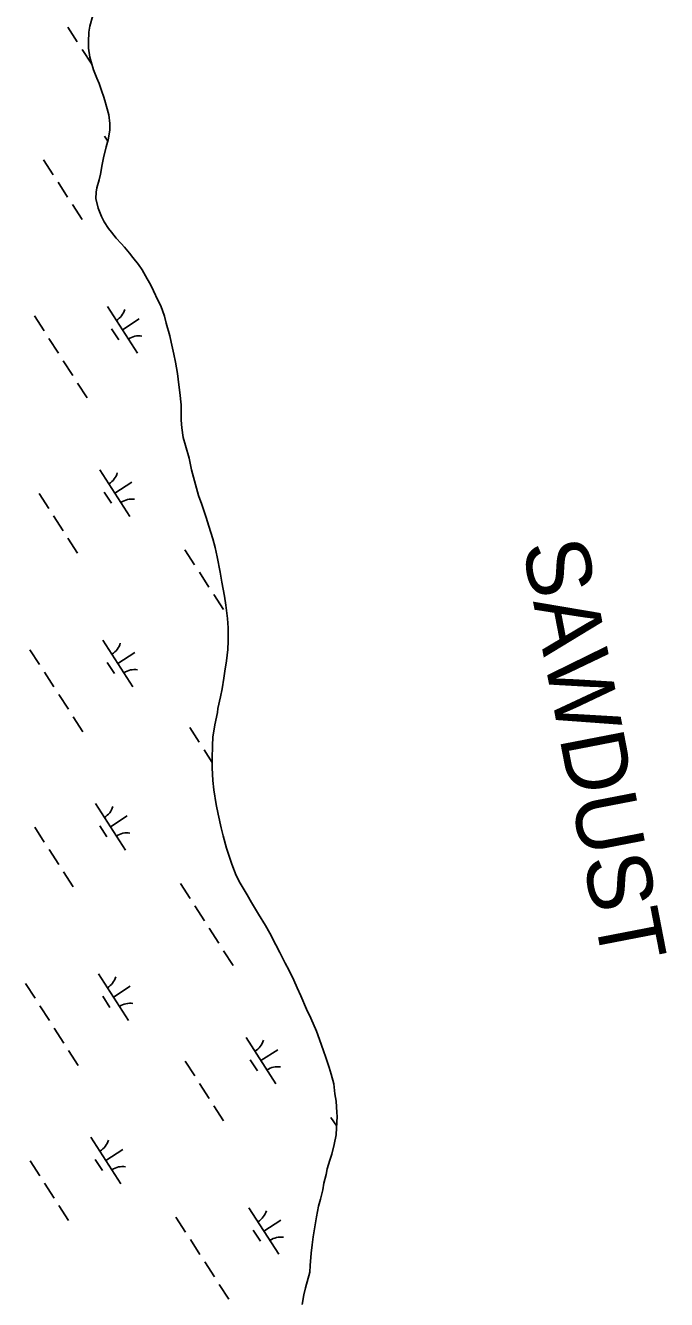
# Model space of a CAD drawing. Extents: x 3937982 to 3958556, y 219448 to 241894.
# Drawn here: x 3949983 to 3950561, y 230898 to 232047 of the extents above; entities that cross this region are included whole.
import ezdxf

# ---------------------------------------------------------------- set-up
doc = ezdxf.new("R2010")
doc.units = 0
for name, color, linetype in [('V-RIVR-IDEN', 7, 'Continuous'), ('V-TOPO-SHOR', 7, 'Continuous'), ('V-WETL-SWMP', 7, 'Continuous')]:
    doc.layers.add(name, color=color, linetype=linetype)

msp = doc.modelspace()

# ---------------------------------------------------------------- linework, layer by layer
at = {"layer": 'V-TOPO-SHOR'}
for points in [[(3950039.605, 232032.615), (3950039.955, 232041.17), (3950040.903, 232046.615), (3950043.39, 232056.149)], [(3950199.304, 231235.325), (3950193.039, 231245.597), (3950186.774, 231256.065), (3950182.666, 231262.85), (3950176.401, 231273.317), (3950172.87, 231280.493), (3950168.748, 231290.582), (3950167.566, 231294.074), (3950164.021, 231304.942), (3950161.057, 231316.008), (3950159.276, 231323.385), (3950156.697, 231335.617), (3950154.715, 231344.549), (3950152.714, 231357.754), (3950151.706, 231366.108), (3950151.268, 231377.573), (3950151.233, 231385.539), (3950151.377, 231397.59), (3950151.733, 231405.171), (3950153.627, 231416.257), (3950155.913, 231427.345), (3950156.286, 231431.04), (3950158.571, 231441.544), (3950160.095, 231448.741), (3950161.608, 231458.464), (3950162.552, 231464.688), (3950164.068, 231474.023), (3950165.188, 231484.134), (3950165.545, 231491.908), (3950165.493, 231503.764), (3950164.875, 231512.118), (3950163.462, 231524.16), (3950162.26, 231532.317), (3950159.874, 231545.136), (3950158.475, 231554.069), (3950155.694, 231567.854), (3950153.908, 231576.204), (3950151.737, 231584.163), (3950148.188, 231595.615), (3950145.822, 231603.379), (3950141.884, 231615.022), (3950138.935, 231623.171), (3950132.615, 231646.465), (3950130.432, 231656.95), (3950127.079, 231668.208), (3950125.105, 231675.585), (3950123.706, 231684.129), (3950123.094, 231691.123), (3950123.063, 231698.508), (3950123.032, 231705.115), (3950121.82, 231716.189), (3950121.207, 231722.988), (3950119.995, 231733.284), (3950118.203, 231743.577), (3950116.618, 231750.565), (3950114.044, 231761.437), (3950112.854, 231767.264), (3950109.696, 231778.522), (3950108.113, 231784.928), (3950104.768, 231794.242), (3950102.22, 231799.284), (3950098.102, 231807.816), (3950095.55, 231813.442), (3950092.613, 231818.677), (3950087.913, 231826.82), (3950084.784, 231831.471), (3950079.705, 231837.861), (3950076.577, 231841.93), (3950072.084, 231847.156), (3950069.155, 231850.448), (3950064.662, 231855.482), (3950060.171, 231860.71), (3950057.629, 231864.198), (3950053.716, 231870.205), (3950051.17, 231874.858), (3950048.221, 231882.425), (3950046.046, 231891.162), (3950046.41, 231896.798), (3950047.17, 231900.884), (3950049.081, 231908.082), (3950050.42, 231913.141), (3950051.94, 231921.697), (3950053.079, 231927.729), (3950055.563, 231937.649), (3950057.283, 231944.072), (3950058.801, 231952.823), (3950058.774, 231958.654), (3950057.769, 231966.616), (3950055.794, 231973.993), (3950054.41, 231979.431), (3950053.032, 231983.504), (3950051.653, 231987.774), (3950049.095, 231994.76), (3950046.937, 231999.804), (3950044.184, 232007.177), (3950041.821, 232014.552), (3950040.832, 232018.629), (3950039.629, 232026.787), (3950039.605, 232032.615)], [(3950232.264, 230893.419), (3950233.782, 230902.172), (3950235.504, 230908.398), (3950239.135, 230922.601), (3950239.692, 230928.628), (3950240.422, 230939.708), (3950241.362, 230947.097), (3950242.302, 230954.486), (3950243.436, 230961.489), (3950245.333, 230972.38), (3950247.041, 230982.106), (3950248.761, 230988.332), (3950250.862, 230996.89), (3950252.003, 231002.922), (3950253.914, 231010.51), (3950255.057, 231015.761), (3950257.356, 231023.545), (3950259.081, 231028.995), (3950261.182, 231037.553), (3950262.894, 231046.307), (3950263.449, 231052.723), (3950263.793, 231063.024), (3950263.779, 231066.522), (3950262.956, 231076.82), (3950261.956, 231083.23), (3950260.945, 231092.36), (3950258.575, 231101.095), (3950256.799, 231107.112), (3950253.846, 231116.039), (3950251.681, 231122.248), (3950248.138, 231132.533), (3950245.191, 231139.904), (3950240.09, 231151.543), (3950236.168, 231159.69), (3950231.062, 231171.718), (3950227.921, 231178.894), (3950224.976, 231185.878), (3950220.271, 231195.186), (3950216.941, 231201.197), (3950212.237, 231210.892), (3950208.706, 231217.874), (3950203.22, 231228.345), (3950199.304, 231235.325)]]:
    msp.add_lwpolyline(points, dxfattribs=at)
at = {"layer": 'V-WETL-SWMP'}
for p, q in [((3950020.778, 232045.823), (3950029.438, 232032.369)), ((3950040.904, 232046.615), (3950039.956, 232041.169)), ((3950043.389, 232056.148), (3950040.904, 232046.615)), ((3950039.956, 232041.169), (3950039.604, 232032.616)), ((3950033.768, 232025.642), (3950042.428, 232012.189)), ((3950039.604, 232032.616), (3950039.629, 232026.786)), ((3950039.629, 232026.786), (3950040.831, 232018.629)), ((3950040.831, 232018.629), (3950041.82, 232014.552)), ((3950041.82, 232014.552), (3950044.184, 232007.177)), ((3950044.184, 232007.177), (3950046.937, 231999.804)), ((3950046.937, 231999.804), (3950049.096, 231994.76)), ((3950049.096, 231994.76), (3950051.653, 231987.775)), ((3950051.653, 231987.775), (3950053.032, 231983.505)), ((3950053.032, 231983.505), (3950054.41, 231979.43)), ((3950054.41, 231979.43), (3950055.794, 231973.994)), ((3950055.794, 231973.994), (3950057.769, 231966.617)), ((3950057.769, 231966.617), (3950058.775, 231958.654)), ((3950058.775, 231958.654), (3950058.801, 231952.823)), ((3950053.926, 231947.452), (3950056.936, 231942.774)), ((3950057.284, 231944.071), (3950055.562, 231937.65)), ((3950058.801, 231952.823), (3950057.284, 231944.071)), ((3950055.562, 231937.65), (3950053.079, 231927.728)), ((3949999.06, 231926.054), (3950007.72, 231912.601)), ((3950051.939, 231921.698), (3950050.421, 231913.141)), ((3950053.079, 231927.728), (3950051.939, 231921.698)), ((3950049.082, 231908.082), (3950047.17, 231900.883)), ((3950050.421, 231913.141), (3950049.082, 231908.082)), ((3950012.049, 231905.874), (3950020.709, 231892.42)), ((3950046.41, 231896.798), (3950046.046, 231891.161)), ((3950047.17, 231900.883), (3950046.41, 231896.798)), ((3950025.039, 231885.693), (3950033.699, 231872.239)), ((3950046.046, 231891.161), (3950048.221, 231882.425)), ((3950048.221, 231882.425), (3950051.169, 231874.858)), ((3950051.169, 231874.858), (3950053.716, 231870.205)), ((3950053.716, 231870.205), (3950057.629, 231864.197)), ((3950057.629, 231864.197), (3950060.17, 231860.71)), ((3950060.17, 231860.71), (3950064.663, 231855.482)), ((3950064.663, 231855.482), (3950069.155, 231850.448)), ((3950069.155, 231850.448), (3950072.084, 231847.157)), ((3950072.084, 231847.157), (3950076.577, 231841.929)), ((3950076.577, 231841.929), (3950079.704, 231837.861)), ((3950079.704, 231837.861), (3950084.784, 231831.47)), ((3950084.784, 231831.47), (3950087.914, 231826.819)), ((3950087.914, 231826.819), (3950092.613, 231818.677)), ((3950092.613, 231818.677), (3950095.551, 231813.442)), ((3950095.551, 231813.442), (3950098.102, 231807.817)), ((3950098.102, 231807.817), (3950102.22, 231799.284)), ((3950056.624, 231793.732), (3950083.687, 231751.689)), ((3950102.22, 231799.284), (3950104.768, 231794.242)), ((3950104.768, 231794.242), (3950108.112, 231784.928)), ((3949990.759, 231785.137), (3949999.419, 231771.683)), ((3950070.155, 231772.71), (3950085.291, 231782.453)), ((3950108.112, 231784.928), (3950109.695, 231778.521)), ((3950060.42, 231773.579), (3950066.915, 231763.489)), ((3950109.695, 231778.521), (3950112.853, 231767.263)), ((3950003.749, 231764.956), (3950012.409, 231751.502)), ((3950112.853, 231767.263), (3950114.044, 231761.438)), ((3950114.044, 231761.438), (3950116.618, 231750.565)), ((3950116.618, 231750.565), (3950118.203, 231743.576)), ((3950016.739, 231744.775), (3950025.399, 231731.322)), ((3950118.203, 231743.576), (3950119.996, 231733.283)), ((3950029.729, 231724.595), (3950038.389, 231711.141)), ((3950119.996, 231733.283), (3950121.207, 231722.988)), ((3950121.207, 231722.988), (3950121.819, 231716.189)), ((3950121.819, 231716.189), (3950123.033, 231705.116)), ((3950123.033, 231705.116), (3950123.062, 231698.509)), ((3950123.062, 231698.509), (3950123.094, 231691.124)), ((3950123.094, 231691.124), (3950123.707, 231684.13)), ((3950123.707, 231684.13), (3950125.104, 231675.585)), ((3950125.104, 231675.585), (3950127.08, 231668.208)), ((3950127.08, 231668.208), (3950130.432, 231656.951)), ((3950130.432, 231656.951), (3950132.615, 231646.465)), ((3950049.886, 231646.404), (3950076.949, 231604.361)), ((3950132.615, 231646.465), (3950138.935, 231623.171)), ((3950063.417, 231625.382), (3950078.553, 231635.125)), ((3949995.02, 231625.007), (3950003.68, 231611.553)), ((3950053.682, 231626.251), (3950060.177, 231616.161)), ((3950138.935, 231623.171), (3950141.885, 231615.022)), ((3950141.885, 231615.022), (3950145.823, 231603.378)), ((3950008.01, 231604.826), (3950016.67, 231591.372)), ((3950145.823, 231603.378), (3950148.188, 231595.614)), ((3950148.188, 231595.614), (3950151.736, 231584.163)), ((3950021, 231584.645), (3950029.66, 231571.191)), ((3950126.587, 231574.119), (3950135.247, 231560.665)), ((3950151.736, 231584.163), (3950153.908, 231576.204)), ((3950153.908, 231576.204), (3950155.693, 231567.855)), ((3950155.693, 231567.855), (3950158.474, 231554.069)), ((3950139.577, 231553.938), (3950148.237, 231540.484)), ((3950158.474, 231554.069), (3950159.873, 231545.135)), ((3950159.873, 231545.135), (3950162.26, 231532.318)), ((3950152.567, 231533.757), (3950161.227, 231520.303)), ((3950162.26, 231532.318), (3950163.462, 231524.161)), ((3950163.462, 231524.161), (3950164.874, 231512.118)), ((3950164.874, 231512.118), (3950165.493, 231503.764)), ((3950165.493, 231503.764), (3950165.544, 231491.909)), ((3949986.72, 231484.089), (3949995.38, 231470.635)), ((3950052.585, 231492.684), (3950079.647, 231450.641)), ((3950165.189, 231484.134), (3950164.067, 231474.023)), ((3950165.544, 231491.909), (3950165.189, 231484.134)), ((3950056.381, 231472.532), (3950062.876, 231462.441)), ((3950066.116, 231471.662), (3950081.252, 231481.405)), ((3950164.067, 231474.023), (3950162.553, 231464.688)), ((3949999.71, 231463.908), (3950008.37, 231450.455)), ((3950162.553, 231464.688), (3950161.608, 231458.464)), ((3950160.095, 231448.741), (3950158.571, 231441.543)), ((3950161.608, 231458.464), (3950160.095, 231448.741)), ((3950012.7, 231443.728), (3950021.36, 231430.274)), ((3950158.571, 231441.543), (3950156.285, 231431.039)), ((3950155.912, 231427.345), (3950153.628, 231416.257)), ((3950156.285, 231431.039), (3950155.912, 231427.345)), ((3950025.69, 231423.547), (3950034.349, 231410.093)), ((3950130.848, 231413.988), (3950139.508, 231400.535)), ((3950153.628, 231416.257), (3950151.732, 231405.171)), ((3950151.732, 231405.171), (3950151.376, 231397.59)), ((3950143.838, 231393.808), (3950151.248, 231382.296)), ((3950151.376, 231397.59), (3950151.234, 231385.54)), ((3950151.234, 231385.54), (3950151.268, 231377.572)), ((3950151.268, 231377.572), (3950151.706, 231366.108)), ((3950151.706, 231366.108), (3950152.714, 231357.755)), ((3950152.714, 231357.755), (3950154.715, 231344.548)), ((3950045.847, 231345.356), (3950072.909, 231303.313)), ((3950154.715, 231344.548), (3950156.697, 231335.617)), ((3950059.378, 231324.334), (3950074.514, 231334.077)), ((3950156.697, 231335.617), (3950159.276, 231323.384)), ((3949990.981, 231323.959), (3949999.641, 231310.505)), ((3950049.643, 231325.204), (3950056.138, 231315.113)), ((3950159.276, 231323.384), (3950161.057, 231316.007)), ((3950161.057, 231316.007), (3950164.02, 231304.942)), ((3950003.971, 231303.778), (3950012.631, 231290.324)), ((3950164.02, 231304.942), (3950167.565, 231294.074)), ((3950167.565, 231294.074), (3950168.747, 231290.581)), ((3950168.747, 231290.581), (3950172.871, 231280.493)), ((3950016.961, 231283.597), (3950025.62, 231270.144)), ((3950172.871, 231280.493), (3950176.401, 231273.317)), ((3950122.548, 231273.071), (3950131.208, 231259.617)), ((3950176.401, 231273.317), (3950182.665, 231262.85)), ((3950135.538, 231252.89), (3950144.198, 231239.436)), ((3950182.665, 231262.85), (3950186.775, 231256.065)), ((3950186.775, 231256.065), (3950193.04, 231245.598)), ((3950193.04, 231245.598), (3950199.303, 231235.325)), ((3950148.527, 231232.709), (3950157.187, 231219.256)), ((3950199.303, 231235.325), (3950203.22, 231228.345)), ((3950203.22, 231228.345), (3950208.707, 231217.874)), ((3950208.707, 231217.874), (3950212.236, 231210.893)), ((3950161.517, 231212.529), (3950170.177, 231199.075)), ((3950212.236, 231210.893), (3950216.942, 231201.196)), ((3950216.942, 231201.196), (3950220.272, 231195.186)), ((3950220.272, 231195.186), (3950224.976, 231185.878)), ((3950048.545, 231191.636), (3950075.608, 231149.593)), ((3950224.976, 231185.878), (3950227.921, 231178.894)), ((3949982.68, 231183.041), (3949991.34, 231169.588)), ((3950062.077, 231170.615), (3950077.212, 231180.357)), ((3950227.921, 231178.894), (3950231.062, 231171.717)), ((3950231.062, 231171.717), (3950236.167, 231159.689)), ((3949995.67, 231162.861), (3950004.33, 231149.407)), ((3950052.341, 231171.484), (3950058.836, 231161.394)), ((3950236.167, 231159.689), (3950240.089, 231151.544)), ((3950240.089, 231151.544), (3950245.192, 231139.905)), ((3950008.66, 231142.68), (3950017.32, 231129.226)), ((3950245.192, 231139.905), (3950248.139, 231132.533)), ((3950181.675, 231134.338), (3950208.737, 231092.295)), ((3950248.139, 231132.533), (3950251.682, 231122.248)), ((3950021.65, 231122.499), (3950030.31, 231109.045)), ((3950195.206, 231113.316), (3950210.341, 231123.059)), ((3950251.682, 231122.248), (3950253.847, 231116.038)), ((3950253.847, 231116.038), (3950256.8, 231107.111)), ((3950126.809, 231112.941), (3950135.469, 231099.487)), ((3950185.471, 231114.185), (3950191.966, 231104.095)), ((3950256.8, 231107.111), (3950258.576, 231101.094)), ((3950139.798, 231092.76), (3950148.458, 231079.306)), ((3950258.576, 231101.094), (3950260.945, 231092.359)), ((3950260.945, 231092.359), (3950261.957, 231083.229)), ((3950261.957, 231083.229), (3950262.956, 231076.82)), ((3950152.788, 231072.579), (3950161.448, 231059.125)), ((3950262.956, 231076.82), (3950263.778, 231066.523)), ((3950258.376, 231062.053), (3950263.495, 231054.099)), ((3950263.793, 231063.025), (3950263.449, 231052.723)), ((3950263.778, 231066.523), (3950263.793, 231063.025)), ((3950262.894, 231046.307), (3950261.182, 231037.554)), ((3950263.449, 231052.723), (3950262.894, 231046.307)), ((3950041.807, 231044.308), (3950068.87, 231002.265)), ((3950261.182, 231037.554), (3950259.081, 231028.994)), ((3949986.941, 231022.911), (3949995.601, 231009.457)), ((3950045.603, 231024.156), (3950052.098, 231014.065)), ((3950055.339, 231023.287), (3950070.474, 231033.029)), ((3950257.356, 231023.545), (3950255.057, 231015.761)), ((3950259.081, 231028.994), (3950257.356, 231023.545)), ((3950255.057, 231015.761), (3950253.914, 231010.509)), ((3949999.931, 231002.73), (3950008.591, 230989.277)), ((3950252.003, 231002.921), (3950250.863, 230996.891)), ((3950253.914, 231010.509), (3950252.003, 231002.921)), ((3950248.762, 230988.331), (3950247.04, 230982.105)), ((3950250.863, 230996.891), (3950248.762, 230988.331)), ((3950012.921, 230982.55), (3950021.581, 230969.096)), ((3950184.373, 230980.618), (3950211.436, 230938.575)), ((3950247.04, 230982.105), (3950245.333, 230972.38)), ((3950118.508, 230972.023), (3950127.168, 230958.569)), ((3950197.904, 230959.596), (3950213.04, 230969.339)), ((3950245.333, 230972.38), (3950243.437, 230961.489)), ((3950188.169, 230960.466), (3950194.664, 230950.375)), ((3950242.301, 230954.487), (3950241.361, 230947.098)), ((3950243.437, 230961.489), (3950242.301, 230954.487)), ((3950131.498, 230951.842), (3950140.158, 230938.389)), ((3950241.361, 230947.098), (3950240.421, 230939.709)), ((3950144.488, 230931.662), (3950153.148, 230918.208)), ((3950240.421, 230939.709), (3950239.692, 230928.628)), ((3950239.135, 230922.601), (3950235.504, 230908.398)), ((3950239.692, 230928.628), (3950239.135, 230922.601)), ((3950157.478, 230911.481), (3950166.138, 230898.027)), ((3950235.504, 230908.398), (3950233.782, 230902.172)), ((3950233.782, 230902.172), (3950232.265, 230893.419))]:
    msp.add_line(p, q, dxfattribs=at)
for centre, start, end in [((3950055.405, 231796.065), 301.99668, 343.540338), ((3950085.305, 231749.613), 81.996677, 123.540335), ((3950048.667, 231648.737), 301.99668, 343.540338), ((3950078.567, 231602.285), 81.996677, 123.540335), ((3950051.366, 231495.017), 301.99668, 343.540338), ((3950081.266, 231448.565), 81.996677, 123.540335), ((3950044.628, 231347.689), 301.99668, 343.540338), ((3950074.528, 231301.237), 81.996677, 123.540335), ((3950047.326, 231193.969), 301.99668, 343.540338), ((3950077.226, 231147.517), 81.996677, 123.540335), ((3950180.455, 231136.671), 301.99668, 343.540338), ((3950210.355, 231090.219), 81.996677, 123.540335), ((3950040.588, 231046.641), 301.99668, 343.540338), ((3950070.488, 231000.189), 81.996677, 123.540335), ((3950183.154, 230982.951), 301.99668, 343.540338), ((3950213.054, 230936.499), 81.996677, 123.540335)]:
    msp.add_arc(centre, 17.623, start, end, dxfattribs=at)

# ---------------------------------------------------------------- texts
at = {"layer": 'V-RIVR-IDEN'}
msp.add_text('SAWDUST', height=57.9999, rotation=280.969605, dxfattribs=at).set_placement((3950430.749, 231578.406))

doc.saveas('drawing.dxf')
